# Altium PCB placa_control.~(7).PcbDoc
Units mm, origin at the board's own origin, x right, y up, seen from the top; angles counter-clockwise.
Board outline 152.4 x 101.6 mm, 2 copper layers (Top Layer, Bottom Layer); 34 components, 26 nets, 130 pads, 100 vias.
Unrouted connection lines stored in the file: 67.
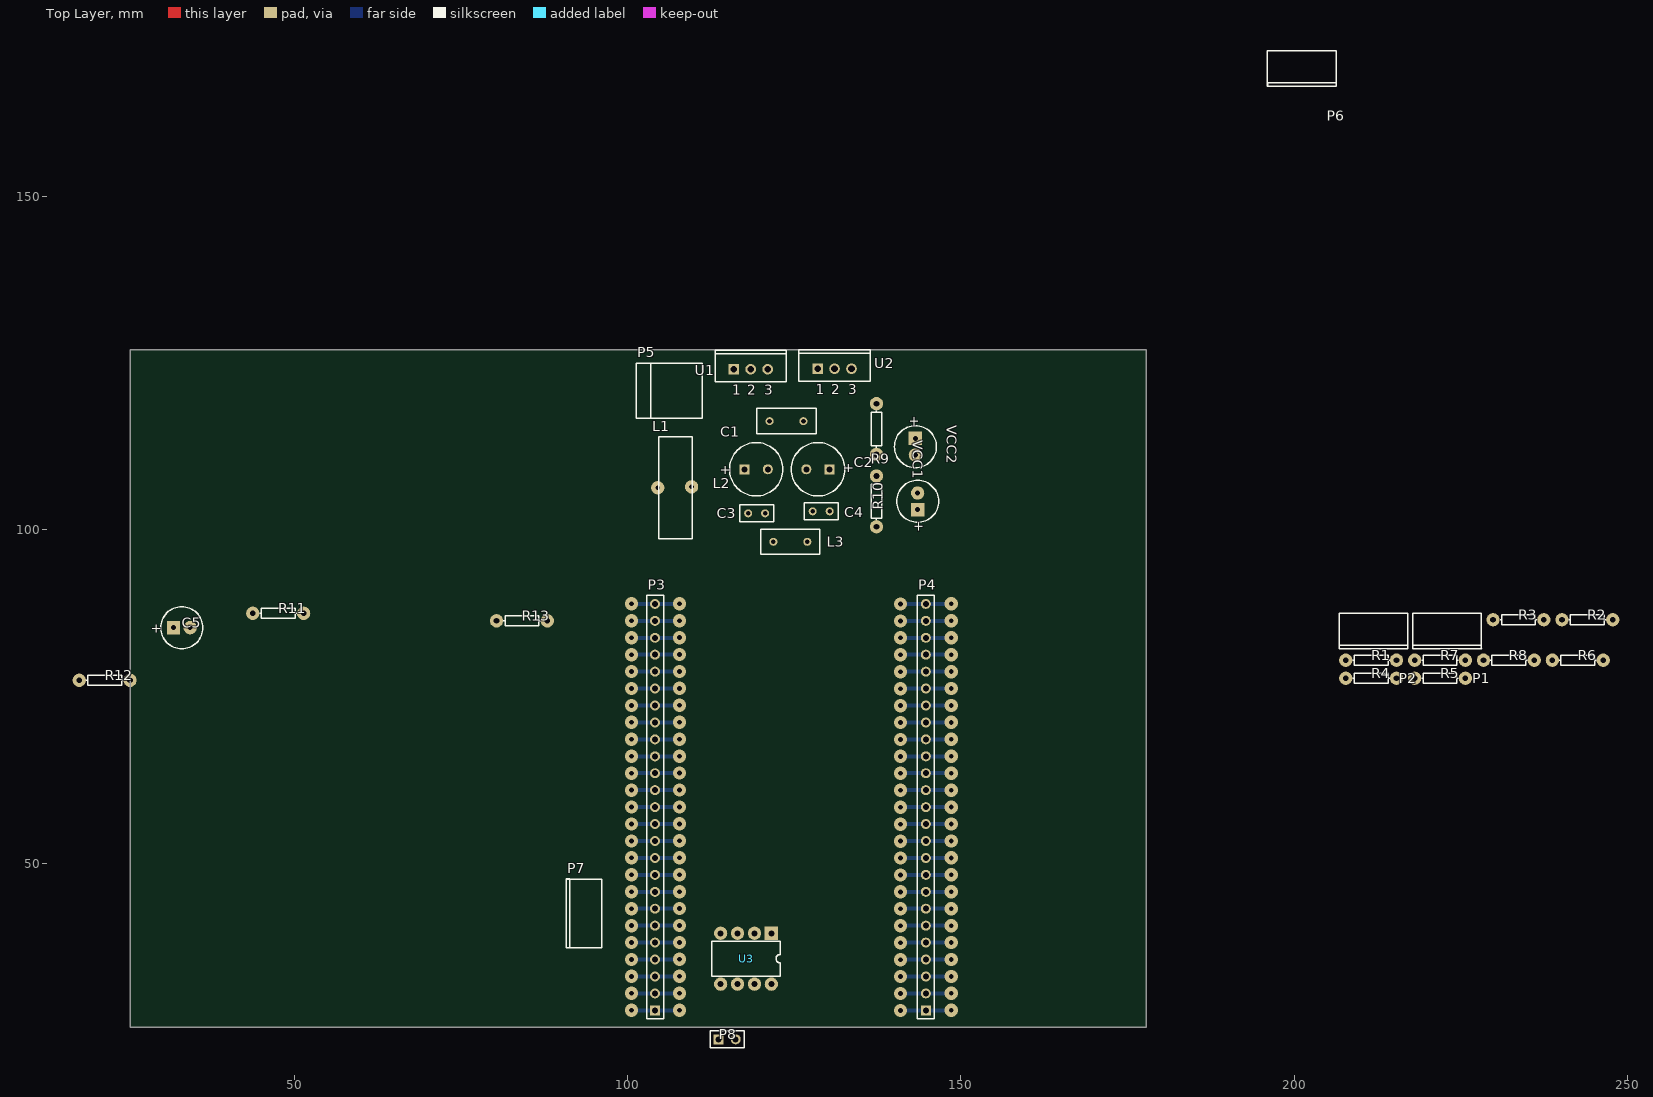
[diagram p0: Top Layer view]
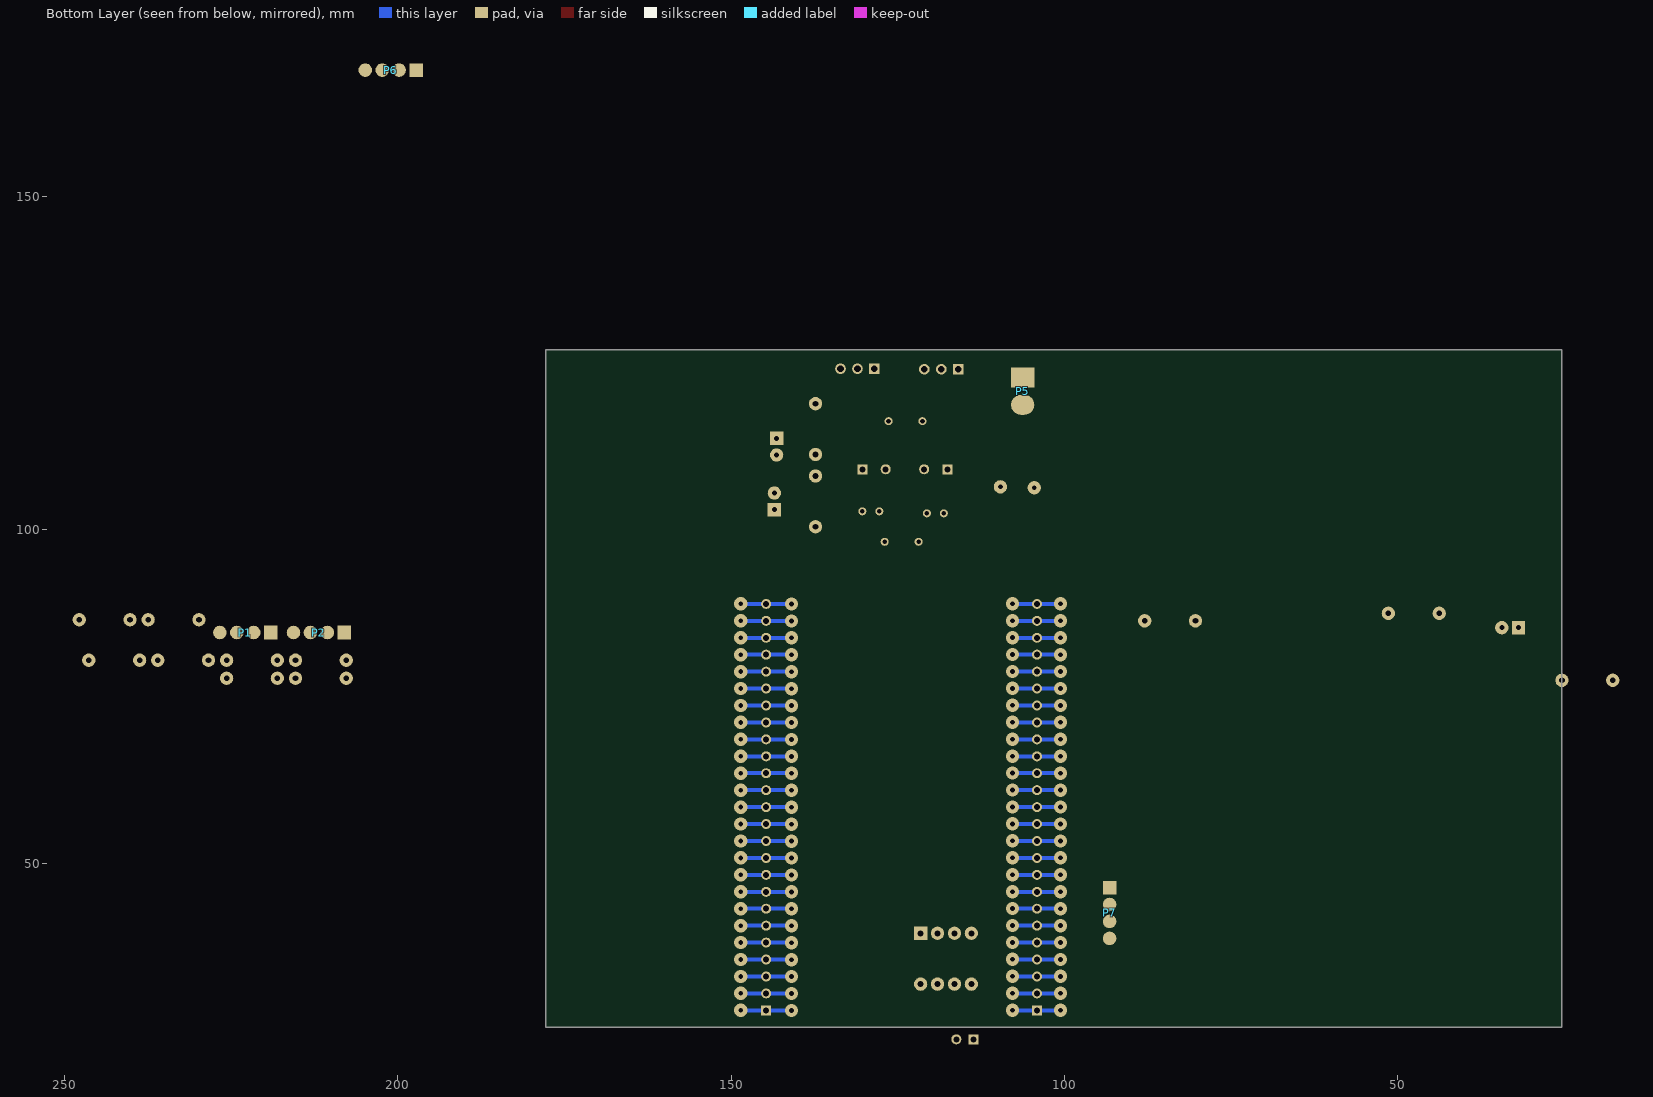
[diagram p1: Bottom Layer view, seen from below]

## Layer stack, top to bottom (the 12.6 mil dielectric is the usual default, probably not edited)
Top Layer: signal copper 0.0356
Dielectric: dielectric 0.32, FR-4, Dk 4.8
Bottom Layer: signal copper 0.0356

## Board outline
25.4,25.4 177.8,25.4 177.8,127 25.4,127

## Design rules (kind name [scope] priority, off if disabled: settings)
Clearance [All] p1: gap=0.254
ComponentClearance [All] p1: gap=0.254 collisioncheckmode=3 verticalgap=0.254
PolygonConnect [All] p1: connectstyle=Relief reliefconductorwidth=0.254 reliefentries=4 polygonreliefangle="90 Angle"
RoomDefinition REGULADOR [InComponentClass('REGULADOR')] p1: confinementstyle=ConfineOut formatcopy=TRUE lockcomponents=FALSE outline 94.85,122.159 93.453,122.159 93.453,110.475 94.85,110.475
RoomDefinition INTERFAZ [InComponentClass('INTERFAZ')] p2: confinementstyle=ConfineIn formatcopy=TRUE lockcomponents=FALSE outline 19.575,27.975 70.375,27.975 70.375,53.375 19.575,53.375
RoomDefinition ENCODER [InComponentClass('ENCODER')] p3: confinementstyle=ConfineIn formatcopy=TRUE lockcomponents=FALSE outline 206.375,62.738 257.175,62.738 257.175,88.138 206.375,88.138
RoomDefinition BOARD-ARM [InComponentClass('BOARD-ARM')] p4: confinementstyle=ConfineOut formatcopy=TRUE lockcomponents=FALSE outline 166.025,120.7 232.827,120.7 232.827,146.1 166.025,146.1
RoomDefinition placa_control_esquema [InComponentClass('placa_control_esquema')] p5: confinementstyle=ConfineIn formatcopy=TRUE lockcomponents=FALSE outline 129.325,143.075 180.125,143.075 180.125,168.475 129.325,168.475
RoutingVias [All] p1: holewidth=0.711 width=2 viastyle="Through Hole" minholewidth=0.711 minwidth=1.27 maxholewidth=0.711 maxwidth=2
SolderMaskExpansion [All] p1: expansion=0.102
TestPointUsage [All] p1: valid=0 allowmultiple=FALSE
Testpoint [All] p1: side=15 testpointundercomponent=TRUE minsize=1.016 maxsize=2.54 preferedsize=1.524 minholesize=0 maxholesize=1.016 preferedholesize=0.813 testpointgrid=0.025 style=1023 order=0123456789
Width [All] p1: maxlimit=1 minlimit=0.6 preferedwidth=0.8
18 further rules are at their usual default settings.

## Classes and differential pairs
component class placa_control_esquema: P6 P7
component class REGULADOR: C1 C2 C3 C4 L1 L2 L3 P5 R9 R10 U1 U2 VCC1 VCC2
component class BOARD-ARM: P3 P4
component class ENCODER: P1 P2 R1 R2 R3 R4 R5 R6 R7 R8
component class INTERFAZ: C5 P8 R11 R12 R13 U3

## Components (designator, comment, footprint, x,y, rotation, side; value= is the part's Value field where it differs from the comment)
C1 "Cap Pol3" CAPPR3.5-8X15 119.305,109.095 r0 top
C2 "Cap Pol3" CAPPR3.5-8X15 128.576,109.095 r180 top
C3 "Cap" RAD-0.1 119.376,102.486 r180 top
C4 "Cap" RAD-0.1 129.053,102.791 r0 top
C5 "Cap" CAPPR2.5-6.3X5 33.157,85.334 r0 top
L1 "Inductor Iron" bobina_Choque 104.663,108.865 r270 top
L2 "Inductor" RAD-0.2 123.851,116.309 r0 top
L3 "Inductor" RAD-0.2 124.431,98.219 r0 top
P1 "Header 4" HDR1X5 226.695,76.989 r0 top
P2 "Header 4" HDR1X5 215.646,76.989 r0 top
P3 "Header 25" HDR1X25 104.14,27.94 r90 top
P4 "Header 25" HDR1X25 144.755,27.94 r90 top
P5 "Header 2" pwheader1x2 106.286,120.665 r270 top
P6 "Header 4" HDR1X5 204.881,161.349 r0 top
P7 "Header 4" HDR1X5 85.623,38.735 r270 top
P8 "Header 2" HDR1X2 113.69,23.597 r0 top
R1 "metal film 2%" AXIAL-0.3 211.541,80.459 r0 top
R2 "metal film 2%" AXIAL-0.3 243.97,86.528 r0 top
R3 "metal film 2%" AXIAL-0.3 233.639,86.528 r0 top
R4 "metal film 2%" AXIAL-0.3 211.541,77.748 r0 top
R5 "metal film 2%" AXIAL-0.3 221.872,77.748 r0 top
R6 "metal film 2%" AXIAL-0.3 242.534,80.459 r0 top
R7 "metal film 2%" AXIAL-0.3 221.872,80.459 r0 top
R8 "metal film 2%" AXIAL-0.3 232.203,80.459 r0 top
R9 "Carbon 1/8w 5%" AXIAL-0.3 137.346,104.279 r90 top
R10 "Carbon 1/8w 5%" AXIAL-0.3 137.346,115.125 r90 top
R11 "Carbon 1/8w 5%" AXIAL-0.3 47.615,87.482 r0 top
R12 "Carbon 1/8w 5%" AXIAL-0.3 21.586,77.438 r0 top
R13 "Carbon 1/8w 5%" AXIAL-0.3 84.176,86.36 r0 top
U1 "LM78L12ACZ" T03B 118.48,124.099 r0 top
U2 "LM78L05ACZ" T03B 131.062,124.165 r0 top
U3 "SN75176BP" 626-05 117.78,35.687 r180 top
VCC1 "LED2" CAPPR2.5-6.3X5 143.518,104.279 r90 top
VCC2 "LED2" CAPPR2.5-6.3X5 143.188,112.484 r270 top

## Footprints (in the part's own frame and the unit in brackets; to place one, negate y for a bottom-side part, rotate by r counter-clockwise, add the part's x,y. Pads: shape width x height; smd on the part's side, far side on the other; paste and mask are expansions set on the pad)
626-05 [mm] "DIP; 8 Leads; Row Spacing 7.62 mm; Pitch 2.54 mm"
  rect 2x2 hole 0.9: 1(-3.81,-3.81)
  round 2 hole 0.9: 2(-1.27,-3.81) 3(1.27,-3.81) 4(3.81,-3.81) 5(3.81,3.81) 6(1.27,3.81) 7(-1.27,3.81) 8(-3.81,3.81)
  silkscreen extent -5.15,-2.65 5.15,2.65
AXIAL-0.3 [mm] "Resistor; 2 Leads"
  round 2 hole 0.85: 1(-3.81,0) 2(3.81,0)
  silkscreen extent -2.77,-0.76 2.77,0.76
bobina_Choque [mm]
  round 2 hole 0.7: 1(2.54,-0.127) 2(2.413,4.953)
  silkscreen extent -5.08,0 10.16,5.08
CAPPR2.5-6.3X5 [mm] "Capacitor, Electrolytic, Radial; Body 6.3 x 5 mm (Dia.xH typ); Pin Spacing 2.5 mm (typ)"
  rect 2x2 hole 0.75: 1(-1.25,0)
  round 2 hole 0.75: 2(1.25,0)
  silkscreen extent -3.15,-3.15 3.15,3.15
CAPPR3.5-8X15 [mm] "Capacitor, Electrolytic, Radial; Body 8 x 15 mm (Dia.xH typ); Pin Spacing 3.5 mm (typ)"
  rect 1.5x1.5 hole 0.9: 1(-1.75,0)
  round 1.5 hole 0.9: 2(1.75,0)
  silkscreen extent -4,-4 4,4
HDR1X2 [mm] "Connector; Header; 2 Position"
  rect 1.5x1.5 hole 0.9: 1(0,0)
  round 1.5 hole 0.9: 2(2.54,0)
  silkscreen extent -1.27,-1.27 3.81,1.27
HDR1X5 [mil]
  rect 80x80 smd far side: 1(-300,300)
  round 80 smd far side: 2(-200,300) 3(-100,300) 4(0,300)
  silkscreen extent -350,205 55,415
HDR1X25 [mm] "Connector; Header; 25 Position"
  rect 1.5x1.5 hole 0.9: 1(0,0)
  round 1.5 hole 0.9: 2(2.54,0) 3(5.08,0) 4(7.62,0) 5(10.16,0) 6(12.7,0) 7(15.24,0) 8(17.78,0) 9(20.32,0) 10(22.86,0) 11(25.4,0) 12(27.94,0) 13(30.48,0) 14(33.02,0) 15(35.56,0) 16(38.1,0) 17(40.64,0) 18(43.18,0) 19(45.72,0) 20(48.26,0) 21(50.8,0) 22(53.34,0) 23(55.88,0) 24(58.42,0) 25(60.96,0)
  silkscreen extent -1.27,-1.27 62.23,1.27
pwheader1x2 [mm]
  rect 3x3.5 smd far side: 1(-2.159,0)
  oval 3x3.5 smd far side: 2(1.905,0)
  silkscreen extent -4.32,-4.95 3.94,4.95
RAD-0.1 [mm] "Indicating Instrument; 2 Leads"
  round 1.2 hole 0.7: 1(-1.27,0) 2(1.27,0)
  silkscreen extent -2.54,-1.27 2.54,1.27
RAD-0.2 [mm] "Jumper Wire; 2 Leads"
  round 1.2 hole 0.7: 1(-2.54,0) 2(2.54,0)
  silkscreen extent -4.44,-1.91 4.44,1.91
T03B [mm] "TO, Thru-Hole, Vertical, Heatsink Mounted; 3 In-Line Leads; Pitch 2.54 mm"
  rect 1.6x1.6 hole 1: 1(-2.54,0)
  round 1.6 hole 1: 2(0,0) 3(2.54,0)
  silkscreen extent -5.35,-1.85 5.35,2.85

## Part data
C1: "Polarized Capacitor (Surface Mount)"
C2: "Polarized Capacitor 35V"
C3 C4 C5: "Capacitor"
L1: "Magnetic-Core Inductor"
P1 P2 P6 P7: "Header, 4-Pin"
P3 P4: "Header, 25-Pin"
P5 P8: "Header, 2-Pin"
R1 R2 R3 R4 R5 R6 R7 R8 R9 R10 R11 R12 R13: library part "Res Semi", "Semiconductor Resistor"
U1 U2: "3-Terminal Positive Regulator"
U3: "Differential Bus Transceiver"
VCC1 VCC2: "Typical RED, GREEN, YELLOW, AMBER GaAs LED"

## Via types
v1: diameter 2, hole 0.711, Top Layer to Bottom Layer, 100 vias

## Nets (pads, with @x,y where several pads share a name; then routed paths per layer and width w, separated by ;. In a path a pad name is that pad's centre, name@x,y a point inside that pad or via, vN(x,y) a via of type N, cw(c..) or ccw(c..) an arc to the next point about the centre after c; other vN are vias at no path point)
+5V: C5.2 P4.2 R10.2 R11.2 U2.3 U3.8 | length 7.2
  Bottom Layer w0.6: v1@141.255,30.48 v1@148.44,30.48
  other v1: 140.95,30.465 148.575,30.485
+12V: P1.1 P2.1 P6.4 P7.4 R9.2 U1.3 U2.1
GND: C2.2 C4.1 C5.1 L3.2 P1.2 P2.2 P4.1 P6.3 P7.3 R2.1 R4.1 R6.1 R8.1 R13.1 U1.2 U2.2 U3.5 VCC1.2 VCC2.2 | length 7.2
  Bottom Layer w0.6: v1@141.255,27.94 v1@148.44,27.94
  other v1: 140.95,27.925 148.575,27.945
IN_SD_1: P4.21 P6.2 | length 7.2
  Bottom Layer w0.6: v1@141.255,78.74 v1@148.44,78.74
  other v1: 140.95,78.725 148.575,78.745
IN_SD_2: P3.19 P7.2 | length 7.2
  Bottom Layer w0.6: v1@100.64,73.66 v1@107.825,73.66
  other v1: 100.6,73.67 107.8,73.685
NetC1_1: C1.1 C3.2 L1.2 L2.1
NetC1_2: C1.2 C3.1 L3.1 P5.1
NetC2_1: C2.1 C4.2 L2.2 U1.1
NetL1_1: L1.1 P5.2
NetP1_3: P1.3 R1.2
NetP1_4: P1.4 R3.2
NetP2_3: P2.3 R5.2
NetP2_4: P2.4 R7.2
NetP3_6: P3.6 U3.2 U3.3 | length 7.2
  Bottom Layer w0.6: v1@100.64,40.64 v1@107.825,40.64
  other v1: 100.6,40.65 107.8,40.665
NetP3_7: P3.7 U3.1 | length 7.2
  Bottom Layer w0.6: v1@100.64,43.18 v1@107.825,43.18
  other v1: 100.6,43.19 107.8,43.205
NetP3_8: P3.8 U3.4 | length 7.2
  Bottom Layer w0.6: v1@100.64,45.72 v1@107.825,45.72
  other v1: 100.6,45.73 107.8,45.745
NetP3_20: P3.20 R7.1 R8.2 | length 7.2
  Bottom Layer w0.6: v1@100.64,76.2 v1@107.825,76.2
  other v1: 100.6,76.21 107.8,76.225
NetP3_21: P3.21 R5.1 R6.2 | length 7.2
  Bottom Layer w0.6: v1@100.64,78.74 v1@107.825,78.74
  other v1: 100.6,78.75 107.8,78.765
NetP4_14: P4.14 R3.1 R4.2 | length 7.2
  Bottom Layer w0.6: v1@141.255,60.96 v1@148.44,60.96
  other v1: 140.95,60.945 148.575,60.965
NetP4_15: P4.15 R1.1 R2.2 | length 7.2
  Bottom Layer w0.6: v1@141.255,63.5 v1@148.44,63.5
  other v1: 140.95,63.485 148.575,63.505
NetP8_1: P8.1 R11.1 R12.2 U3.6
NetP8_2: P8.2 R12.1 R13.2 U3.7
NetR9_1: R9.1 VCC1.1
NetR10_1: R10.1 VCC2.1
PWM_1: P4.16 P6.1 | length 7.2
  Bottom Layer w0.6: v1@141.255,66.04 v1@148.44,66.04
  other v1: 140.95,66.025 148.575,66.045
PWM_2: P3.9 P7.1 | length 7.2
  Bottom Layer w0.6: v1@100.64,48.26 v1@107.825,48.26
  other v1: 100.6,48.27 107.8,48.285
pads on no net: P3.1 P3.2 P3.3 P3.4 P3.5 P3.10 P3.11 P3.12 P3.13 P3.14 P3.15 P3.16 P3.17 P3.18 P3.22 P3.23 P3.24 P3.25 P4.3 P4.4 P4.5 P4.6 P4.7 P4.8 P4.9 P4.10 P4.11 P4.12 P4.13 P4.17 P4.18 P4.19 P4.20 P4.22 P4.23 P4.24 P4.25
copper on no net: | length 265.8
  Bottom Layer w0.6: v1@100.64,27.94 v1@107.825,27.94 ; v1@100.64,30.48 v1@107.825,30.48 ; v1@100.64,33.02 v1@107.825,33.02 ; v1@100.64,35.56 v1@107.825,35.56 ; v1@100.64,38.1 v1@107.825,38.1 ; v1@100.64,50.8 v1@107.825,50.8 ; v1@100.64,53.34 v1@107.825,53.34 ; v1@100.64,55.88 v1@107.825,55.88 ; v1@100.64,58.42 v1@107.825,58.42 ; v1@100.64,60.96 v1@107.825,60.96 ; v1@100.64,63.5 v1@107.825,63.5 ; v1@100.64,66.04 v1@107.825,66.04 ; v1@100.64,68.58 v1@107.825,68.58 ; v1@100.64,71.12 v1@107.825,71.12 ; v1@100.64,81.28 v1@107.825,81.28 ; v1@100.64,83.82 v1@107.825,83.82 ; v1@100.64,86.36 v1@107.825,86.36 ; v1@100.64,88.9 v1@107.825,88.9 ; v1@141.255,33.02 v1@148.44,33.02 ; v1@141.255,35.56 v1@148.44,35.56 ; v1@141.255,38.1 v1@148.44,38.1 ; v1@141.255,40.64 v1@148.44,40.64 ; v1@141.255,43.18 v1@148.44,43.18 ; v1@141.255,45.72 v1@148.44,45.72 ; v1@141.255,48.26 v1@148.44,48.26 ; v1@141.255,50.8 v1@148.44,50.8 ; v1@141.255,53.34 v1@148.44,53.34 ; v1@141.255,55.88 v1@148.44,55.88 ; v1@141.255,58.42 v1@148.44,58.42 ; v1@141.255,68.58 v1@148.44,68.58 ; v1@141.255,71.12 v1@148.44,71.12 ; v1@141.255,73.66 v1@148.44,73.66 ; v1@141.255,76.2 v1@148.44,76.2 ; v1@141.255,81.28 v1@148.44,81.28 ; v1@141.255,83.82 v1@148.44,83.82 ; v1@141.255,86.36 v1@148.44,86.36 ; v1@141.255,88.9 v1@148.44,88.9
  other v1: 100.6,27.95 107.8,27.965 100.6,30.49 107.8,30.505 140.95,33.005 100.6,33.03 148.575,33.025 107.8,33.045 140.95,35.545 100.6,35.57 148.575,35.565 107.8,35.585 140.95,38.085 100.6,38.11 148.575,38.105 107.8,38.125 140.95,40.625 148.575,40.645 140.95,43.165 148.575,43.185 140.95,45.705 148.575,45.725 140.95,48.245 148.575,48.265 140.95,50.785 100.6,50.81 148.575,50.805 107.8,50.825 140.95,53.325 100.6,53.35 148.575,53.345 107.8,53.365 140.95,55.865 100.6,55.89 148.575,55.885 107.8,55.905 140.95,58.405 100.6,58.43 148.575,58.425 107.8,58.445 100.6,60.97 107.8,60.985 100.6,63.51 107.8,63.525 100.6,66.05 107.8,66.065 140.95,68.565 100.6,68.59 148.575,68.585 107.8,68.605 140.95,71.105 100.6,71.13 148.575,71.125 107.8,71.145 140.95,73.645 148.575,73.665 140.95,76.185 148.575,76.205 140.95,81.265 100.6,81.29 148.575,81.285 107.8,81.305 140.95,83.805 100.6,83.83 148.575,83.825 107.8,83.845 140.95,86.345 100.6,86.37 148.575,86.365 107.8,86.385 140.95,88.885 100.6,88.91 148.575,88.905 107.8,88.925

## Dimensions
145.174,22.567 to 104.574,21.342 on Top Layer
